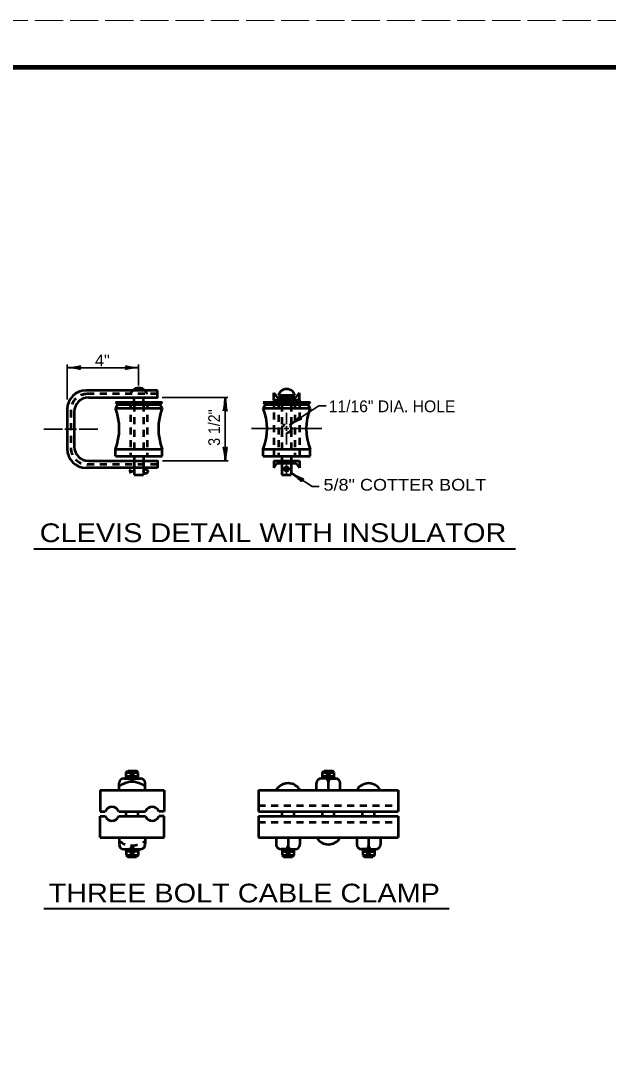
# Model space of a CAD drawing. Extents: x -1 to 679, y 0 to 440.
# Drawn here: x 228.3 to 353.6, y 220.2 to 440.2 of the extents above; entities that cross this region are included whole.
import ezdxf

# ---------------------------------------------------------------- set-up
doc = ezdxf.new("R2010")
doc.units = 0
doc.linetypes.add('LONG_DASHED', pattern=[7.5, 6, -1.5])
doc.linetypes.add('SHORT_DASHED', pattern=[2.7, 1.5, -1.2])
doc.layers.add('1', color=7, linetype='Continuous', lineweight=53)
doc.layers.add('61', color=7, linetype='Continuous', lineweight=35)

msp = doc.modelspace()

# ---------------------------------------------------------------- linework, layer by layer
at = {"layer": '1', "lineweight": 35}
for p, q in [((238.275, 359.415), (238.275, 366.927)), ((238.275, 366.233), (253.475, 366.233)), ((253.475, 362.427), (253.475, 366.927)), ((258.525, 359.877), (272.525, 359.877)), ((271.953, 346.371), (271.953, 359.877)), ((285.025, 356.627), (285.025, 354.152)), ((233.275, 353.124), (237.275, 353.124)), ((237.775, 353.124), (240.275, 353.124)), ((240.775, 353.124), (244.775, 353.124)), ((284.061, 353.252), (277.525, 353.252)), ((285.025, 353.252), (284.525, 353.252)), ((285.025, 353.752), (285.025, 352.752)), ((285.525, 353.252), (285.025, 353.252)), ((285.025, 352.352), (285.025, 349.877)), ((292.525, 353.252), (285.992, 353.252)), ((258.54, 346.371), (272.54, 346.371)), ((285.025, 343.621), (285.025, 345.627))]:
    msp.add_line(p, q, dxfattribs=at)
at = {"layer": '1'}
for p, q in [((257.525, 361.377), (242.275, 361.377)), ((282.275, 359.377), (282.275, 360.877)), ((282.275, 360.877), (283.025, 359.877)), ((287.025, 359.877), (287.775, 360.877)), ((287.775, 359.377), (287.775, 360.877)), ((248.525, 358.877), (258.525, 358.877)), ((248.525, 358.877), (249.025, 358.377)), ((252.525, 358.877), (252.525, 359.877)), ((254.525, 358.877), (254.525, 359.877)), ((258.525, 358.877), (258.025, 358.377)), ((280.025, 358.877), (290.025, 358.877)), ((280.025, 358.877), (280.525, 358.377)), ((282.275, 359.377), (287.775, 359.377)), ((283.025, 359.877), (287.025, 359.877)), ((283.275, 360.377), (286.775, 360.377)), ((284.025, 358.877), (284.025, 359.377)), ((286.025, 358.877), (286.025, 359.377)), ((290.025, 358.877), (289.525, 358.377)), ((238.275, 357.377), (238.275, 348.871)), ((239.775, 356.877), (239.775, 349.371)), ((248.525, 357.627), (249.025, 358.377)), ((248.525, 357.627), (258.525, 357.627)), ((249.025, 358.377), (258.025, 358.377)), ((258.525, 357.627), (258.025, 358.377)), ((280.025, 357.627), (280.525, 358.377)), ((280.025, 357.627), (290.025, 357.627)), ((280.525, 358.377), (289.525, 358.377)), ((290.025, 357.627), (289.525, 358.377)), ((248.525, 348.877), (258.525, 348.877)), ((248.525, 347.377), (248.525, 348.877)), ((258.525, 347.377), (258.525, 348.877)), ((280.025, 348.877), (290.025, 348.877)), ((280.025, 347.377), (280.025, 348.877)), ((290.025, 347.377), (290.025, 348.877)), ((248.525, 347.377), (258.525, 347.377)), ((252.525, 347.377), (252.525, 346.371)), ((254.525, 347.377), (254.525, 346.371)), ((280.025, 347.377), (290.025, 347.377)), ((282.275, 346.377), (287.775, 346.377)), ((282.275, 346.377), (282.275, 344.877)), ((282.275, 344.877), (283.025, 345.877)), ((283.025, 345.877), (287.025, 345.877)), ((284.025, 347.377), (284.025, 346.377)), ((284.025, 345.877), (284.025, 343.371)), ((286.025, 347.377), (286.025, 346.377)), ((286.025, 345.877), (286.025, 343.371)), ((287.025, 345.877), (287.775, 344.877)), ((287.775, 346.377), (287.775, 344.877)), ((257.54, 344.871), (242.275, 344.871)), ((252.025, 344.121), (251.484, 343.809)), ((252.525, 344.871), (252.525, 343.371)), ((252.525, 343.371), (254.525, 343.371)), ((254.525, 344.871), (254.525, 343.371)), ((284.025, 343.371), (286.025, 343.371)), ((250.835, 279.907), (251.195, 280.267)), ((250.835, 279.907), (253.355, 279.907)), ((250.835, 278.647), (250.835, 279.907)), ((251.195, 280.267), (252.995, 280.267)), ((251.595, 279.507), (252.595, 279.507)), ((253.355, 279.907), (252.995, 280.267)), ((253.355, 278.647), (253.355, 279.907)), ((292.675, 279.907), (293.015, 280.267)), ((292.675, 278.647), (292.675, 279.907)), ((292.675, 279.907), (295.195, 279.907)), ((293.015, 280.267), (294.835, 280.267)), ((293.415, 279.507), (294.435, 279.507)), ((295.195, 279.907), (294.835, 280.267)), ((295.195, 278.647), (295.195, 279.907)), ((249.315, 276.127), (249.315, 277.647)), ((250.335, 278.647), (253.855, 278.647)), ((250.835, 279.107), (253.355, 279.107)), ((254.875, 276.127), (254.875, 277.647)), ((291.415, 276.127), (291.415, 277.647)), ((293.935, 278.647), (292.415, 278.647)), ((292.675, 279.107), (295.195, 279.107)), ((293.935, 278.647), (295.435, 278.647)), ((293.935, 276.127), (293.935, 277.887)), ((296.455, 276.127), (296.455, 277.647)), ((245.295, 276.127), (258.895, 276.127)), ((245.295, 276.127), (245.295, 271.587)), ((258.895, 276.127), (258.895, 271.587)), ((279.055, 276.127), (308.795, 276.127)), ((279.055, 276.127), (279.055, 271.587)), ((308.795, 276.127), (308.795, 271.587)), ((245.295, 271.587), (246.375, 271.587)), ((249.235, 271.587), (254.955, 271.587)), ((250.835, 270.587), (250.835, 271.587)), ((253.355, 270.587), (253.355, 271.587)), ((258.895, 271.587), (257.795, 271.587)), ((279.055, 271.587), (308.795, 271.587)), ((284.095, 270.587), (284.095, 271.587)), ((286.615, 270.587), (286.615, 271.587)), ((292.675, 270.587), (292.675, 271.587)), ((295.195, 270.587), (295.195, 271.587)), ((301.235, 270.587), (301.235, 271.587)), ((303.755, 270.587), (303.755, 271.587)), ((245.295, 266.047), (245.295, 270.587)), ((245.295, 270.587), (246.375, 270.587)), ((249.235, 270.587), (254.935, 270.587)), ((258.895, 270.587), (257.795, 270.587)), ((258.895, 266.047), (258.895, 270.587)), ((279.055, 270.587), (279.055, 266.047)), ((308.795, 270.587), (308.795, 266.047)), ((245.295, 266.047), (258.895, 266.047)), ((249.315, 266.087), (249.315, 264.587)), ((254.875, 266.087), (254.875, 264.587)), ((279.055, 266.047), (308.795, 266.047)), ((282.815, 266.067), (282.815, 264.547)), ((285.335, 266.067), (285.335, 264.287)), ((287.855, 266.067), (287.855, 264.547)), ((299.995, 266.047), (299.995, 264.527)), ((302.515, 266.047), (302.515, 264.287)), ((305.035, 266.047), (305.035, 264.527)), ((250.335, 263.567), (253.855, 263.567)), ((250.835, 263.567), (250.835, 262.307)), ((250.835, 263.127), (253.355, 263.127)), ((250.835, 262.307), (251.195, 261.947)), ((250.835, 262.307), (253.355, 262.307)), ((251.195, 261.947), (252.995, 261.947)), ((251.595, 262.707), (252.595, 262.707)), ((253.355, 262.307), (252.995, 261.947)), ((253.355, 263.567), (253.355, 262.307)), ((285.335, 263.547), (283.835, 263.547)), ((284.075, 263.547), (284.075, 262.287)), ((284.075, 263.087), (286.595, 263.087)), ((284.075, 262.287), (284.435, 261.927)), ((284.075, 262.287), (286.595, 262.287)), ((284.435, 261.927), (286.255, 261.927)), ((284.835, 262.687), (285.855, 262.687)), ((285.335, 263.547), (286.855, 263.547)), ((286.595, 262.287), (286.255, 261.927)), ((286.595, 263.547), (286.595, 262.287)), ((302.515, 263.527), (300.995, 263.527)), ((301.255, 263.527), (301.255, 262.267)), ((301.255, 263.067), (303.775, 263.067)), ((301.255, 262.267), (301.615, 261.907)), ((301.255, 262.267), (303.775, 262.267)), ((301.615, 261.907), (303.415, 261.907)), ((302.015, 262.667), (303.015, 262.667)), ((302.515, 263.527), (304.035, 263.527)), ((303.775, 262.267), (303.415, 261.907)), ((303.775, 263.527), (303.775, 262.267))]:
    msp.add_line(p, q, dxfattribs=at)
at = {"layer": '1', "linetype": 'SHORT_DASHED'}
for p, q in [((257.525, 360.627), (242.525, 360.627)), ((251.775, 358.877), (251.775, 347.377)), ((255.275, 358.877), (255.275, 347.377)), ((282.275, 359.377), (282.275, 346.377)), ((283.275, 358.877), (283.275, 347.377)), ((286.775, 358.877), (286.775, 347.377)), ((287.775, 359.377), (287.775, 346.377)), ((239.025, 357.127), (239.025, 349.121)), ((252.525, 358.377), (252.525, 347.377)), ((254.525, 358.377), (254.525, 347.377)), ((284.025, 358.377), (284.025, 347.377)), ((286.025, 358.377), (286.025, 347.377)), ((257.54, 345.621), (242.525, 345.621)), ((252.525, 346.371), (252.525, 344.871)), ((254.525, 346.371), (254.525, 344.871)), ((279.055, 272.847), (308.795, 272.847)), ((279.055, 269.327), (308.795, 269.327))]:
    msp.add_line(p, q, dxfattribs=at)
at = {"layer": '1', "lineweight": 40}
for p, q in [((231.162, 327.613), (333.846, 327.613)), ((233.257, 250.927), (319.649, 250.927))]:
    msp.add_line(p, q, dxfattribs=at)
at = {"layer": '1', "lineweight": 13}
msp.add_line((249.235, 271.587), (249.315, 271.587), dxfattribs=at)
at = {"layer": '1'}
for points in [[(242.775, 359.877), (257.525, 359.877), (257.525, 361.377)], [(242.775, 346.371), (257.54, 346.371), (257.54, 344.871)], [(252.525, 344.121), (252.025, 344.121), (251.484, 344.434)], [(279.055, 270.587), (284.095, 270.587), (286.615, 270.587), (301.235, 270.587)], [(301.235, 270.587), (303.755, 270.587), (308.795, 270.587)]]:
    msp.add_lwpolyline(points, dxfattribs=at)
at = {"layer": '1', "lineweight": 35}
for points in [[(285.623, 354.014), (291.917, 358.13), (293.475, 358.13)], [(286.025, 343.788), (290.462, 340.911), (291.951, 340.911)]]:
    msp.add_lwpolyline(points, dxfattribs=at)
at = {"layer": '1', "linetype": 'SHORT_DASHED'}
msp.add_circle((285.026, 353.255), 0.966, dxfattribs=at)
at = {"layer": '1'}
for centre in [(254.979, 344.112), (285.018, 344.621)]:
    msp.add_circle(centre, 0.449, dxfattribs=at)
for centre, radius, start, end in [((242.275, 357.377), 4, 90, 180), ((253.525, 360.099), 1.828, 44.35198, 135.64802), ((285.025, 359.849), 1.828, 135.64802, 163.217), ((285.025, 359.849), 1.828, 44.35198, 135.64802), ((285.025, 359.849), 1.828, 16.783, 44.35198), ((242.775, 356.877), 3, 90, 180), ((237.343, 353.252), 12.008, 338.63221, 21.36779), ((269.708, 353.252), 12.008, 158.63221, 201.36779), ((268.843, 353.252), 12.008, 338.63221, 21.36779), ((301.208, 353.252), 12.008, 158.63221, 201.36779), ((242.275, 348.871), 4, 180, 270), ((242.775, 349.371), 3, 180, 270), ((250.33, 277.643), 1.008, 90, 180), ((252.094, 273.58), 4.316, 50.03379, 129.96621), ((250.757, 277.549), 1.382, 14.49718, 52.88295), ((253.425, 277.549), 1.382, 127.11705, 165.50282), ((253.858, 277.643), 1.008, 0, 90), ((285.345, 274.733), 2.885, 29.14172, 150.85828), ((292.414, 277.643), 1.008, 90, 180), ((293.039, 277.85), 0.889, 2.94427, 64.43586), ((294.814, 277.85), 0.889, 115.56414, 177.05572), ((295.438, 277.643), 1.008, 0, 90), ((302.513, 274.722), 2.885, 29.14172, 150.85828), ((247.806, 271.091), 1.512, 19.49795, 160.50177), ((256.371, 271.088), 1.512, 19.58943, 160.41041), ((247.806, 271.091), 1.512, 199.44421, 340.55538), ((256.371, 271.088), 1.512, 199.35299, 340.6469), ((250.33, 264.581), 1.008, 180, 270), ((250.757, 264.674), 1.382, 307.11705, 345.50282), ((253.425, 264.674), 1.382, 194.49718, 232.88295), ((253.858, 264.581), 1.008, 270, 0), ((283.833, 264.546), 1.008, 180, 270), ((284.457, 264.34), 0.889, 295.56414, 357.05572), ((286.232, 264.34), 0.889, 182.94427, 244.43586), ((286.857, 264.546), 1.008, 270, 0), ((293.926, 267.456), 2.885, 209.14172, 330.85828), ((301.001, 264.535), 1.008, 180, 270), ((301.626, 264.329), 0.889, 295.56414, 357.05572), ((303.401, 264.329), 0.889, 182.94427, 244.43586), ((304.025, 264.535), 1.008, 270, 0)]:
    msp.add_arc(centre, radius, start, end, dxfattribs=at)
at = {"layer": '1', "linetype": 'SHORT_DASHED'}
for centre, radius, start, end in [((253.525, 360.099), 1.828, 135.64802, 163.217), ((253.525, 360.099), 1.828, 16.783, 44.35198), ((242.525, 357.127), 3.5, 90, 180), ((242.525, 349.121), 3.5, 180, 270), ((252.094, 268.644), 4.316, 230.03379, 309.96621)]:
    msp.add_arc(centre, radius, start, end, dxfattribs=at)
at = {"layer": '1', "lineweight": 13}
msp.add_arc((247.806, 271.091), 1.512, 199.26221, 340.15338, dxfattribs=at)
at = {"layer": '1', "lineweight": 40}
for centre, major_axis, ratio, start_param, end_param in [((239.396, 366.021), (-1.756, 0.176), 0.07063, 3.1407148, 5.41811), ((239.367, 366.509), (-1.786, -0.156), 0.122415, 0.8963533, 3.1415927), ((252.384, 365.957), (1.786, 0.156), 0.122415, 0.8963533, 3.1415927), ((252.355, 366.445), (1.756, -0.176), 0.07063, 3.1407148, 5.41811), ((271.742, 358.757), (0.176, 1.756), 0.07063, 3.1407148, 5.41811), ((272.229, 358.786), (-0.156, 1.786), 0.122415, 0.8963533, 3.1415927), ((286.385, 354.842), (-1.409, -1.108), 0.122415, 0.8963533, 3.1415927), ((286.677, 354.45), (1.566, 0.814), 0.07063, 6.2823074, 8.5597026), ((271.677, 347.463), (0.156, -1.786), 0.122415, 0.8963533, 3.1415927), ((272.165, 347.492), (-0.176, -1.756), 0.07063, 3.1407148, 5.41811), ((286.85, 343.001), (-1.378, 1.103), 0.07063, 3.1407148, 5.41811), ((287.091, 343.426), (-1.583, 0.841), 0.122415, 0.8963533, 3.1415927)]:
    msp.add_ellipse(centre, major_axis=major_axis, ratio=ratio, start_param=start_param, end_param=end_param, dxfattribs=at)
at = {"layer": '61', "linetype": 'LONG_DASHED', "lineweight": 13}
msp.add_line((-1.129, 440.242), (678.891, 440.242), dxfattribs=at)
at = {"layer": '61', "lineweight": 158}
msp.add_lwpolyline([(667.911, 430.242), (28.871, 430.242), (28.871, 10.222)], dxfattribs=at)

# ---------------------------------------------------------------- texts
at = {"layer": '1'}
for s, height, width, p in [('4"', 2.5, 1.05, (244.155, 366.537)), ('5/8" COTTER BOLT', 2.5, 1.15, (292.886, 340.01)), ('CLEVIS DETAIL WITH INSULATOR', 4, 1.15, (232.401, 329.03)), ('THREE BOLT CABLE CLAMP', 4, 1.15, (234.292, 252.188))]:
    msp.add_text(s, height=height, dxfattribs=dict(at, width=width)).set_placement(p)
msp.add_text('11/16" DIA. HOLE', height=2.5, dxfattribs=at).set_placement((293.995, 356.744))
at = {"layer": '1', "width": 0.9}
msp.add_text('3 1/2"', height=2.5, rotation=90, dxfattribs=at).set_placement((270.826, 349.577))

doc.saveas('drawing.dxf')
